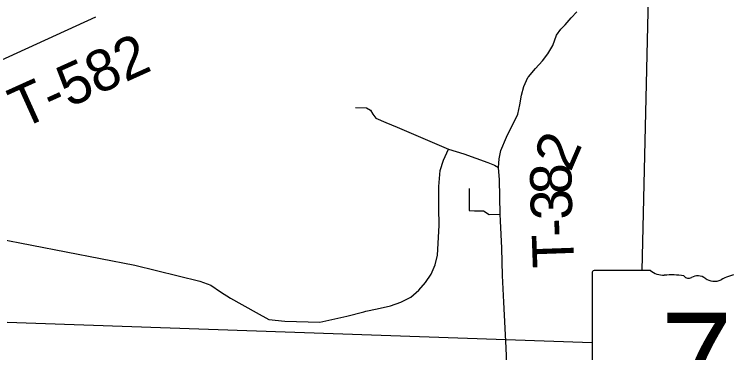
# Model space of a CAD drawing. Extents: x 2.1 to 8.9, y 14.1 to 20.9.
# Drawn here: x 6.556 to 7.533, y 14.992 to 15.456 of the extents above; entities that cross this region are included whole.
import ezdxf

# ---------------------------------------------------------------- set-up
doc = ezdxf.new("R2010")
doc.units = 0
for name, color, linetype in [('GM_X_City_Street', 7, 'Continuous'), ('GM_X_County_Road', 7, 'Continuous'), ('GM_X_Interchange_Ramps', 7, 'Continuous'), ('GM_X_Minor_River_Text', 7, 'Continuous')]:
    doc.layers.add(name, color=color, linetype=linetype)

msp = doc.modelspace()

# ---------------------------------------------------------------- linework, layer by layer
at = {"layer": 'GM_X_City_Street'}
for p, q in [((7.31938, 15.45047), (7.32685, 15.45888)), ((6.52266, 15.3856), (6.6675, 15.45224)), ((7.31098, 15.44103), (7.31938, 15.45047)), ((7.29917, 15.42698), (7.30495, 15.43512)), ((7.30495, 15.43512), (7.31098, 15.44103)), ((7.29432, 15.41281), (7.29917, 15.42698)), ((7.28723, 15.40153), (7.29432, 15.41281)), ((7.27988, 15.39168), (7.28723, 15.40153)), ((7.27056, 15.38131), (7.27988, 15.39168)), ((7.2606, 15.36975), (7.27056, 15.38131)), ((7.25455, 15.35638), (7.25994, 15.36898)), ((7.25994, 15.36898), (7.2606, 15.36975)), ((7.25114, 15.34483), (7.25455, 15.35638)), ((7.24865, 15.33158), (7.25114, 15.34483)), ((7.02371, 15.32792), (7.03864, 15.3273)), ((7.03864, 15.3273), (7.04403, 15.32419)), ((7.24615, 15.31885), (7.24865, 15.33158)), ((7.04403, 15.32419), (7.04735, 15.31858)), ((7.04735, 15.31858), (7.0515, 15.3134)), ((7.23067, 15.2871), (7.24615, 15.31885)), ((7.0515, 15.3134), (7.06499, 15.30738)), ((7.06499, 15.30738), (7.08076, 15.30064)), ((7.08076, 15.30064), (7.15089, 15.27069)), ((7.22269, 15.26887), (7.23067, 15.2871)), ((7.14432, 15.25547), (7.15089, 15.27069)), ((7.15089, 15.27069), (7.17209, 15.26428)), ((7.22068, 15.25761), (7.22269, 15.26887)), ((7.17209, 15.26428), (7.20483, 15.25246)), ((7.21965, 15.2455), (7.22068, 15.25761)), ((7.13986, 15.24129), (7.14432, 15.25547)), ((7.20483, 15.25246), (7.21435, 15.24857)), ((7.21435, 15.24857), (7.21965, 15.2455)), ((7.13868, 15.23053), (7.13986, 15.24129)), ((7.22109, 15.22883), (7.21965, 15.2455)), ((7.13789, 15.21964), (7.13868, 15.23053)), ((7.22193, 15.18164), (7.22109, 15.22883)), ((7.13789, 15.20626), (7.13789, 15.21964)), ((7.17951, 15.21658), (7.17949, 15.18647)), ((7.13763, 15.19038), (7.13789, 15.20626)), ((7.13828, 15.16597), (7.13763, 15.19038)), ((7.17949, 15.18647), (7.18682, 15.18631)), ((7.18682, 15.18631), (7.19904, 15.18605)), ((7.19904, 15.18605), (7.20665, 15.18133)), ((7.20665, 15.18133), (7.22193, 15.18164)), ((7.22255, 15.17247), (7.22193, 15.18164)), ((6.40011, 15.17409), (6.72128, 15.1117)), ((7.22436, 15.13514), (7.22255, 15.17247)), ((7.13618, 15.12529), (7.13828, 15.16597)), ((7.22526, 15.09754), (7.22436, 15.13514)), ((7.13277, 15.11217), (7.13618, 15.12529)), ((6.72128, 15.1117), (6.81008, 15.08999)), ((7.12726, 15.09957), (7.13277, 15.11217)), ((7.11965, 15.08789), (7.12726, 15.09957)), ((7.22693, 15.06105), (7.22526, 15.09754)), ((6.81008, 15.08999), (6.82531, 15.08448)), ((6.82531, 15.08448), (6.83843, 15.07529)), ((7.1102, 15.07726), (7.11965, 15.08789)), ((6.83843, 15.07529), (6.85207, 15.06637)), ((7.09957, 15.06794), (7.1102, 15.07726)), ((6.85207, 15.06637), (6.88751, 15.04668)), ((7.08593, 15.06125), (7.09957, 15.06794)), ((7.03776, 15.04852), (7.05312, 15.05206)), ((7.05312, 15.05206), (7.07162, 15.05613)), ((7.07162, 15.05613), (7.08593, 15.06125)), ((7.22991, 14.99857), (7.22693, 15.06105)), ((6.88751, 15.04668), (6.90457, 15.0375)), ((7.01191, 15.0417), (7.03489, 15.04776)), ((7.03489, 15.04776), (7.03776, 15.04852)), ((6.90457, 15.0375), (6.92688, 15.03488)), ((6.92688, 15.03488), (6.97447, 15.03343)), ((6.97447, 15.03343), (7.01191, 15.0417)), ((7.23118, 14.97563), (7.22991, 14.99857))]:
    msp.add_line(p, q, dxfattribs=at)
at = {"layer": 'GM_X_County_Road'}
for p, q in [((7.34804, 15.10094), (7.34804, 14.90081)), ((7.42786, 15.10438), (7.35064, 15.10438))]:
    msp.add_line(p, q, dxfattribs=at)
for centre, radius, start, end in [((7.35106, 15.10136), 0.00305, 98.1301, 188.1301), ((7.44624, 15.12761), 0.02963, 231.61951, 271.11188), ((7.45607, 14.99203), 0.10636, 80.48669, 94.98827), ((7.48021, 15.1024), 0.00855, 219.79206, 297.10237), ((7.49276, 15.07927), 0.01777, 54.46668, 119.14113), ((7.5157, 15.11099), 0.02138, 233.85621, 294.82819), ((7.55345, 15.04326), 0.05625, 97.34618, 120.76885)]:
    msp.add_arc(centre, radius, start, end, dxfattribs=at)
at = {"layer": 'GM_X_Interchange_Ramps'}
for p, q in [((7.43801, 16.03935), (7.41618, 15.10438)), ((7.34804, 15.00532), (6.39438, 15.03865))]:
    msp.add_line(p, q, dxfattribs=at)

# ---------------------------------------------------------------- texts
at = {"layer": 'GM_X_County_Road'}
msp.add_text('7', height=0.13184, dxfattribs=at).set_placement((7.4421, 14.91493))
at = {"layer": 'GM_X_Minor_River_Text'}
for s, height, rotation, p in [('T-582', 0.056818, 24.30436, (6.56564, 15.2978)), ('2', 0.05682, 66.64834, (7.31836, 15.23823)), ('8', 0.05682, 90.62972, (7.31998, 15.20936)), ('3', 0.05682, 91.9884, (7.32118, 15.17473)), ('-', 0.05682, 92.07302, (7.32203, 15.15144)), ('T', 0.05682, 92.06178, (7.32356, 15.10895))]:
    msp.add_text(s, height=height, rotation=rotation, dxfattribs=at).set_placement(p)

doc.saveas('drawing.dxf')
